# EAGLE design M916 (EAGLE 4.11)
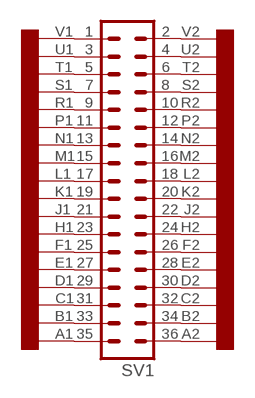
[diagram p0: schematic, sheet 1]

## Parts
SV1  MA18-2  [MA18-2]
U$1  EDGE-2  [EDGE-CON2]

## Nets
N$1: SV1.1 U$1.V1
N$2: SV1.3 U$1.U1
N$3: SV1.5 U$1.T1
N$4: SV1.7 U$1.S1
N$5: SV1.9 U$1.R1
N$6: SV1.11 U$1.P1
N$7: SV1.13 U$1.N1
N$8: SV1.15 U$1.M1
N$9: SV1.17 U$1.L1
N$10: SV1.19 U$1.K1
N$11: SV1.21 U$1.J1
N$12: SV1.23 U$1.H1
N$13: SV1.25 U$1.F1
N$14: SV1.27 U$1.E1
N$15: SV1.29 U$1.D1
N$16: SV1.31 U$1.C1
N$17: SV1.33 U$1.B1
N$18: SV1.35 U$1.A1
N$19: SV1.2 U$1.V2
N$20: SV1.4 U$1.U2
N$21: SV1.6 U$1.T2
N$22: SV1.8 U$1.S2
N$23: SV1.10 U$1.R2
N$24: SV1.12 U$1.P2
N$25: SV1.14 U$1.N2
N$26: SV1.16 U$1.M2
N$27: SV1.18 U$1.L2
N$28: SV1.20 U$1.K2
N$29: SV1.22 U$1.J2
N$30: SV1.24 U$1.H2
N$31: SV1.26 U$1.F2
N$32: SV1.28 U$1.E2
N$33: SV1.30 U$1.D2
N$34: SV1.32 U$1.C2
N$35: SV1.34 U$1.B2
N$36: SV1.36 U$1.A2

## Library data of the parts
SV1 = con-lstb:MA18-2: PIN HEADER
U$1 = dec-con:EDGE-2: Double-Sided DEC edge connector.

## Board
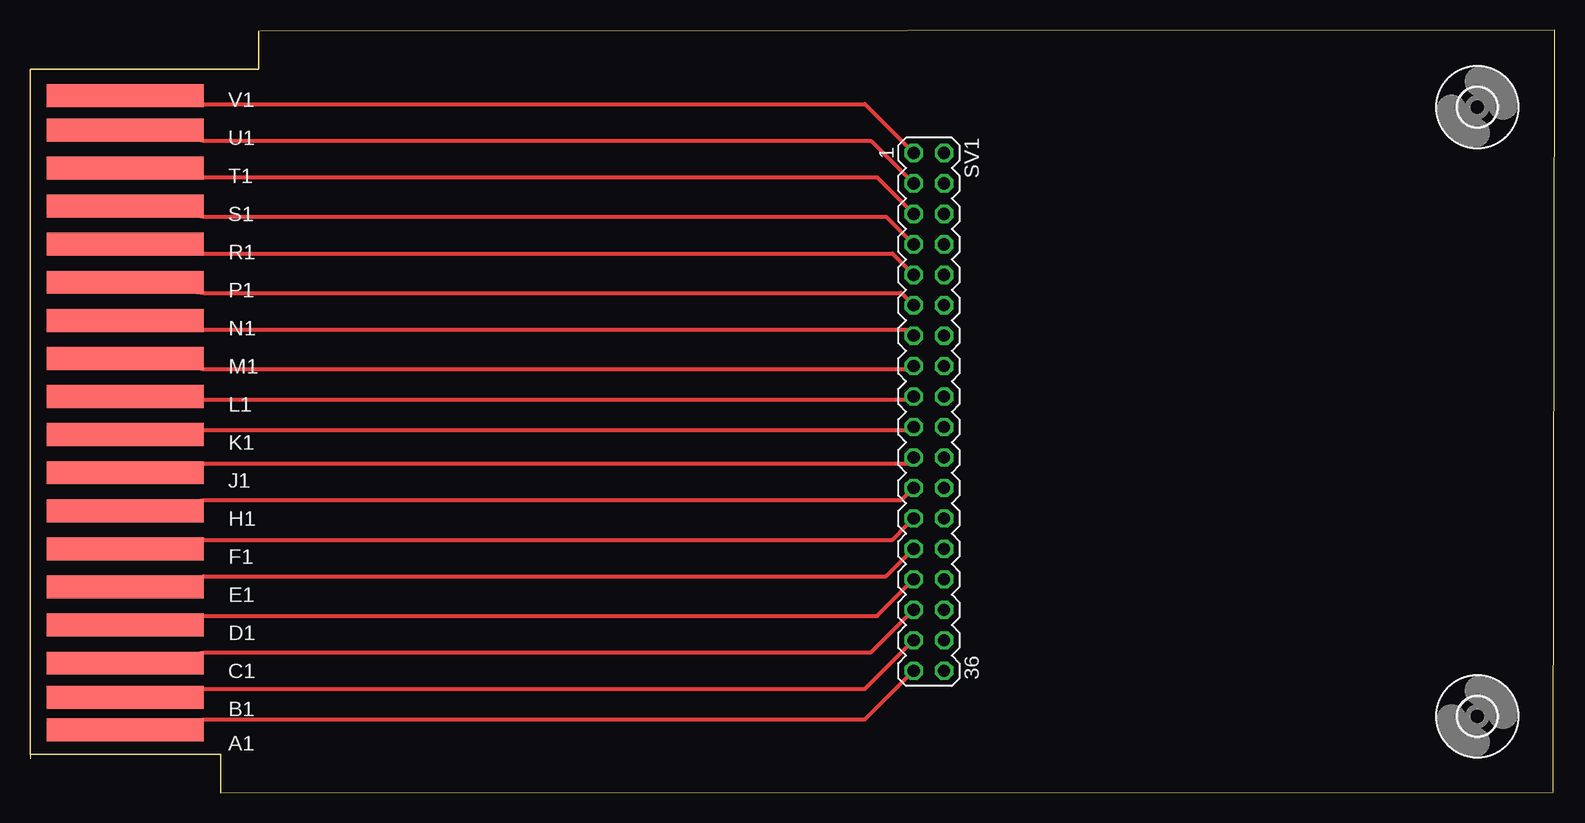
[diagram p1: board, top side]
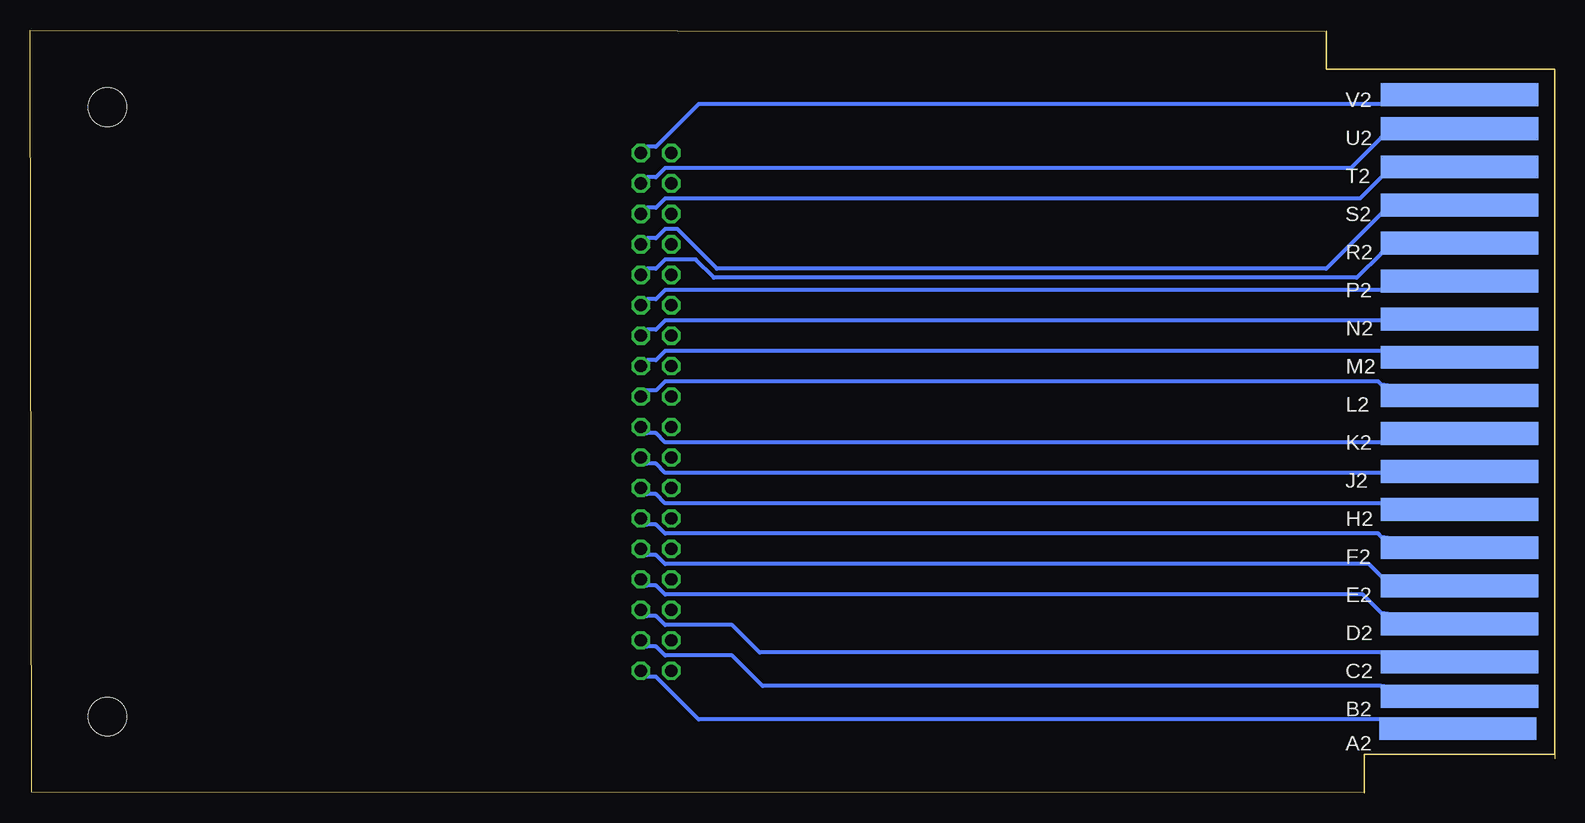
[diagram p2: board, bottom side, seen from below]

Size 127.11 x 63.59 mm. Coordinates in mm from the lower left corner, seen from the top.
Outline: 15.88,0 126.98,0.04 127.11,63.59 19.18,63.5
Outline: 0.01,59.65 0.01,2.83
Copper layers (1*16): Top 0.035mm / dielectric 1.5mm / Bottom 0.035mm
Design rules "10mils": minimum track width 13mil, minimum drill 28mil, track to track 10mil, track to pad 10mil, pad to pad 10mil, via to via 10mil, smd to smd 10mil, copper to edge 40mil, drill to drill 10mil, minimum pad ring 10mil, minimum via ring 8mil, stop-mask expansion 0mil, vias tented up to drill 0mil, thermal gap 10mil

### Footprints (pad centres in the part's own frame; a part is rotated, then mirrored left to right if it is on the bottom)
MA18-2 = drill 1.016 octagon: 1 -21.59,-1.27; 2 -21.59,1.27; 3 -19.05,-1.27; 4 -19.05,1.27; 5 -16.51,-1.27; 6 -16.51,1.27; 7 -13.97,-1.27; 8 -13.97,1.27; 9 -11.43,-1.27; 10 -11.43,1.27; 11 -8.89,-1.27; 12 -8.89,1.27; 13 -6.35,-1.27; 14 -6.35,1.27; 15 -3.81,-1.27; 16 -3.81,1.27; 17 -1.27,-1.27; 18 -1.27,1.27; 19 1.27,-1.27; 20 1.27,1.27; 21 3.81,-1.27; 22 3.81,1.27; 23 6.35,-1.27; 24 6.35,1.27; 25 8.89,-1.27; 26 8.89,1.27; 27 11.43,-1.27; 28 11.43,1.27; 29 13.97,-1.27; 30 13.97,1.27; 31 16.51,-1.27; 32 16.51,1.27; 33 19.05,-1.27; 34 19.05,1.27; 35 21.59,-1.27; 36 21.59,1.27
EDGE-CON2 = smd 13.106 x 1.905: A1 7.938,5.239; B1 7.938,7.938; C1 7.938,10.795; D1 7.938,13.97; E1 7.938,17.145; F1 7.938,20.32; H1 7.938,23.495; J1 7.938,26.67; K1 7.938,29.845; L1 7.938,33.02; M1 7.938,36.195; N1 7.938,39.37; P1 7.938,42.545; R1 7.938,45.72; S1 7.938,48.895; T1 7.938,52.07; U1 7.938,55.245; V1 7.938,58.102 | smd 13.106 x 1.905 bottom: A2 8.096,5.34; B2 7.938,8.039; C2 7.938,10.897; D2 7.938,14.072; E2 7.938,17.247; F2 7.938,20.422; H2 7.938,23.597; J2 7.938,26.772; K2 7.938,29.947; L2 7.938,33.122; M2 7.938,36.297; N2 7.938,39.472; P2 7.938,42.647; R2 7.938,45.822; S2 7.938,48.997; T2 7.938,52.172; U2 7.938,55.347; V2 7.938,58.204
3,2 = hole 3.2: 0,0

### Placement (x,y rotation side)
SV1  74.93,31.75 270 top
U$1  0,0 0 top
U$2  [3,2]  120.65,6.35 0 top
U$3  [3,2]  120.65,57.15 0 top

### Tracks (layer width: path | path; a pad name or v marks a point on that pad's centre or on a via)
N$1
  Top 0.33: SV1.1 73.15,53.85 69.6,57.4 14.48,57.4 U$1.V1
N$2
  Top 0.33: SV1.3 73.15,51.31 70.1,54.36 14.48,54.36 U$1.U1
N$3
  Top 0.33: SV1.5 73.15,48.77 70.61,51.31 14.48,51.31 U$1.T1
N$4
  Top 0.33: SV1.7 73.15,46.23 71.37,48.01 14.48,48.01 U$1.S1
N$5
  Top 0.33: SV1.9 73.15,43.69 71.88,44.96 14.48,44.96 U$1.R1
N$6
  Top 0.33: SV1.11 73.15,41.15 72.64,41.66 14.48,41.66 U$1.P1
N$7
  Top 0.33: SV1.13 73.15,38.61 14.48,38.61 U$1.N1
N$8
  Top 0.33: SV1.15 73.15,35.31 14.48,35.31 U$1.M1
N$9
  Top 0.33: SV1.17 73.15,32.77 14.48,32.77 U$1.L1
N$10
  Top 0.33: SV1.19 73.15,30.23 14.48,30.23 U$1.K1
N$11
  Top 0.33: SV1.21 73.15,27.43 14.48,27.43 U$1.J1
N$12
  Top 0.33: SV1.23 73.15,24.89 72.64,24.38 14.48,24.38 U$1.H1
N$13
  Top 0.33: SV1.25 73.15,22.35 71.88,21.08 14.48,21.08 U$1.F1
N$14
  Top 0.33: SV1.27 73.15,19.81 71.37,18.03 14.48,18.03 U$1.E1
N$15
  Top 0.33: SV1.29 73.15,17.27 70.61,14.73 14.48,14.73 U$1.D1
N$16
  Top 0.33: SV1.31 73.15,14.73 70.1,11.68 14.48,11.68 U$1.C1
N$17
  Top 0.33: SV1.33 73.15,12.19 69.6,8.64 14.48,8.64 U$1.B1
N$18
  Top 0.33: SV1.35 73.15,9.65 69.6,6.1 14.48,6.1 U$1.A1
N$19
  Bottom 0.33: SV1.2 75.69,53.85 74.93,53.85 71.37,57.4 14.48,57.4 U$1.V2
N$20
  Bottom 0.33: SV1.4 75.69,51.31 74.93,51.31 74.17,52.07 17.02,52.07 14.48,54.61 U$1.U2
N$21
  Bottom 0.33: SV1.6 75.69,48.77 74.93,48.77 74.17,49.53 16.26,49.53 14.48,51.31 U$1.T2
N$22
  Bottom 0.33: SV1.8 75.69,46.23 74.93,46.23 74.17,46.99 73.15,46.99 69.85,43.69 19.05,43.69 14.48,48.26 U$1.S2
N$23
  Bottom 0.33: SV1.10 75.69,43.69 74.93,43.69 74.17,44.45 71.63,44.45 70.1,42.93 16.51,42.93 14.48,44.96 U$1.R2
N$24
  Bottom 0.33: SV1.12 75.69,41.15 74.93,41.15 74.17,41.91 14.48,41.91 U$1.P2
N$25
  Bottom 0.33: SV1.14 75.69,38.61 74.93,38.61 74.17,39.37 14.48,39.37 U$1.N2
N$26
  Bottom 0.33: SV1.16 75.69,36.07 74.93,36.07 74.17,36.83 14.48,36.83 U$1.M2
N$27
  Bottom 0.33: SV1.18 75.69,33.53 74.93,33.53 74.17,34.29 14.73,34.29 14.48,34.04 U$1.L2
N$28
  Bottom 0.33: SV1.20 75.69,29.97 74.93,29.97 74.17,29.21 14.48,29.21 U$1.K2
N$29
  Bottom 0.33: SV1.22 75.69,27.43 74.93,27.43 74.17,26.67 14.48,26.67 U$1.J2
N$30
  Bottom 0.33: SV1.24 75.69,24.89 74.93,24.89 74.17,24.13 14.48,24.13 U$1.H2
N$31
  Bottom 0.33: SV1.26 75.69,22.35 74.93,22.35 74.17,21.59 14.73,21.59 14.48,21.34 U$1.F2
N$32
  Bottom 0.33: SV1.28 75.69,19.81 74.93,19.81 74.17,19.05 15.49,19.05 14.48,18.03 U$1.E2
N$33
  Bottom 0.33: SV1.30 75.69,17.27 74.93,17.27 74.17,16.51 16,16.51 14.48,14.99 U$1.D2
N$34
  Bottom 0.33: SV1.32 75.69,14.73 74.93,14.73 74.17,13.97 68.58,13.97 66.29,11.68 14.48,11.68 U$1.C2
N$35
  Bottom 0.33: SV1.34 75.69,12.19 74.93,12.19 74.17,11.43 68.58,11.43 66.04,8.89 14.48,8.89 U$1.B2
N$36
  Bottom 0.33: SV1.36 75.69,9.65 74.93,9.65 71.37,6.1 14.48,6.1 U$1.A2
